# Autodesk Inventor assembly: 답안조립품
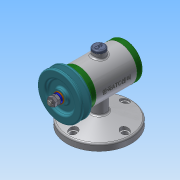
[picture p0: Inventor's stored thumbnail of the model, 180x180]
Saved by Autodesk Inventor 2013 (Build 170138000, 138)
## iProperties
Created: 2018-12
Part Number: 답안조립품
Document SubType Name: Assembly
Designer: Administrator
Author: Administrator
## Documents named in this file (15)
- C:\Users\Administrator\Desktop\481207V1063\답안조립품.iam
- C:\Users\Administrator\Desktop\481207V1063\본체.ipt
- C:\Users\Administrator\Desktop\481207V1063\축.ipt
- C:\Users\Administrator\Desktop\481207V1063\베어링 15 x 32 x 9.ipt
- C:\Users\Administrator\Desktop\481207V1063\뒤커버.ipt
- C:\Users\Administrator\Desktop\481207V1063\볼트 M4 x 12.ipt
- C:\Users\Administrator\Desktop\481207V1063\오일 실 15 25 7.ipt
- C:\Users\Administrator\Desktop\481207V1063\앞커버.ipt
- C:\Users\Administrator\Desktop\481207V1063\V벨트풀리.ipt
- C:\Users\Administrator\Desktop\481207V1063\키 3 x 3 x 12.ipt
- C:\Users\Administrator\Desktop\481207V1063\와셔 8x17.ipt
- C:\Users\Administrator\Desktop\481207V1063\스프링와셔 8.ipt
- C:\Users\Administrator\Desktop\481207V1063\너트 M8.ipt
- 너트 M8.ipt
- C:\Users\Administrator\Desktop\481207V1063\고무캡.ipt
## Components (2 placed, 2 different names)
1. V벨트풀리:1
2. 고무캡:1
